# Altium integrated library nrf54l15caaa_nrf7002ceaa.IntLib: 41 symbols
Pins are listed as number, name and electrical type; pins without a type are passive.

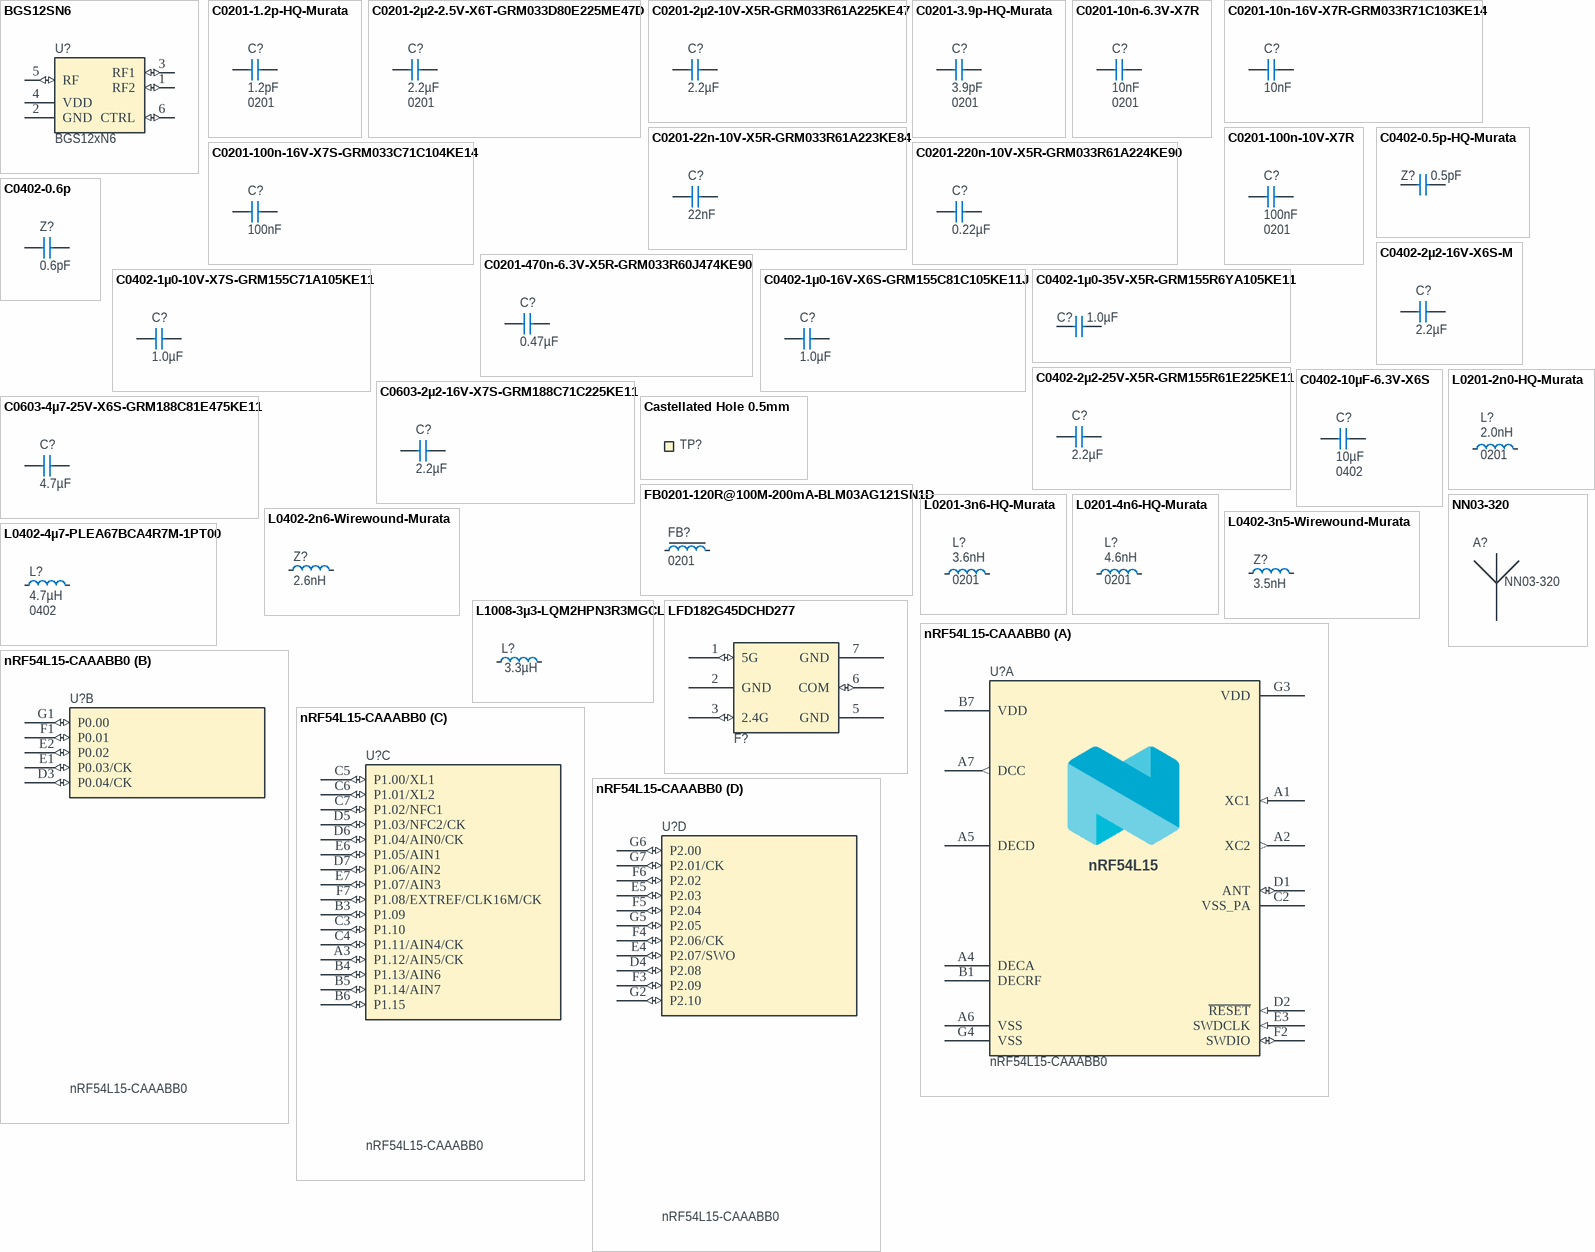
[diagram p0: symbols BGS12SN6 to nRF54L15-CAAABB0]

## BGS12SN6
designator U?, comment BGS12xN6
Wideband SPDT RF Switch, 50MHz-6GHz. Max 30dBm, 1.8-3.5V; Part Number: BGS12SN6; Manufacturer: Infineon Technologies; Manufacturer Part Number: BGS12SN6E6327XTSA1; Component Status: Active; Pad Count: 6; Value: BGS12SN6
footprint TSNP-6-8
pins: 1 RF2 (io), 2 GND (power), 3 RF1 (io), 4 VDD (power), 5 RF (io), 6 CTRL (io), 8 NC hidden

## C0201-1.2p-HQ-Murata
designator C?, comment 1.2pF  Footprint Doc: 0201
Capacitor, NP0, ±0.05pF, 50V; Part Number: C0201-1.2p-HQ-Murata; Manufacturer: Murata; Manufacturer Part Number: GJM0335C1H1R2WB01D; Component Status: Active; Pad Count: 2
footprint CAPC0603X03L_C
pins: 1, 2

## C0201-2µ2-2.5V-X6T-GRM033D80E225ME47D
designator C?, comment 2.2µF  Footprint Doc: 0201
Capacitor, Ceramic, 2.2µF 2.5V X6T 0201,±20%; Part Number: C0201-2µ2-2.5V-X6T-GRM033D80E225ME47D; Manufacturer: Murata; Manufacturer Part Number: GRM033D80E225ME47D; Component Status: Active; Pad Count: 2
footprint CAPC0603X03L_C
pins: 1, 2

## C0201-2µ2-10V-X5R-GRM033R61A225KE47
designator C?, comment 2.2µF
Capacitor, Ceramic, 2.2µF 10V X5R 0201,±10%; Part Number: C0201-2µ2-10V-X5R-GRM033R61A225KE47; Manufacturer: Murata; Manufacturer Part Number: GRM033R61A225KE47D; Pad Count: 2; Component Status: Active
footprint CAPC0603X03L_C
pins: 1, 2

## C0201-3.9p-HQ-Murata
designator C?, comment 3.9pF  Footprint Doc: 0201
Capacitor, NP0, ±0.05pF, 25V; Part Number: C0201-3.9p-HQ-Murata; Manufacturer: Murata; Manufacturer Part Number: GJM0333C1E3R9WB01; Component Status: Active; Pad Count: 2
footprint CAPC0603X03L_C
pins: 1, 2

## C0201-10n-6.3V-X7R
designator C?, comment 10nF  Footprint Doc: 0201
Capacitor, X7R, 6.3V; Part Number: C0201-10n-6.3V-X7R; Manufacturer: Murata; Manufacturer Part Number: GRM033R70J103KA01D; Component Status: Active; Pad Count: 2
footprint CAPC0603X03L_C
pins: 1, 2

## C0201-10n-16V-X7R-GRM033R71C103KE14
designator C?, comment 10nF
Capacitor, Ceramic, 10nF 16V X7R 0201,±10%; Part Number: C0201-10n-16V-X7R-GRM033R71C103KE14; Manufacturer: Murata; Manufacturer Part Number: GRM033R71C103KE14D; Pad Count: 2; Component Status: Active
footprint CAPC0603X03L_C
pins: 1, 2

## C0201-22n-10V-X5R-GRM033R61A223KE84
designator C?, comment 22nF
Capacitor, Ceramic, 22nF 10V X5R 0201,±10%; Part Number: C0201-22n-10V-X5R-GRM033R61A223KE84; Manufacturer: Murata; Manufacturer Part Number: GRM033R61A223KE84D; Pad Count: 2; Component Status: Active
footprint CAPC0603X03L_C
pins: 1, 2

## C0201-100n-10V-X7R
designator C?, comment 100nF  Footprint Doc: 0201
Capacitor, X7R, ±10%; Part Number: C0201-100n-10V-X7R; Manufacturer: N.A.; Pad Count: 2; Component Status: Active
footprint CAPC0603X03L_C
pins: 1, 2

## C0201-100n-16V-X7S-GRM033C71C104KE14
designator C?, comment 100nF
Capacitor, Ceramic, 100nF 16V X7S 0201,±10%; Part Number: C0201-100n-16V-X7S-GRM033C71C104KE14; Manufacturer: Murata; Manufacturer Part Number: GRM033C71C104KE14D; Pad Count: 2; Component Status: Active
footprint CAPC0603X03L_C
pins: 1, 2

## C0201-220n-10V-X5R-GRM033R61A224KE90
designator C?, comment 0.22µF
Capacitor, Ceramic, 0.22µF 10V X5R 0201, ±10%; Part Number: C0201-220n-10V-X5R-GRM033R61A224KE90; Manufacturer: Murata; Manufacturer Part Number: GRM033R61A224KE90D; Pad Count: 2; Component Status: Active
footprint CAPC0603X03L_C
pins: 1, 2

## C0201-470n-6.3V-X5R-GRM033R60J474KE90
designator C?, comment 0.47µF
Capacitor, Ceramic, 0.47µF 6.3V X5R 0201,±10%; Part Number: C0201-470n-6.3V-X5R-GRM033R60J474KE90; Manufacturer: Murata; Manufacturer Part Number: GRM033R60J474KE90D; Pad Count: 2; Component Status: Active
footprint CAPC0603X03L_C
pins: 1, 2

## C0402-0.5p-HQ-Murata
designator Z?, comment 0.5pF
Capacitor, NP0, ±0.05pF, 50V; Part Number: C0402-0.5p-HQ-Murata; Manufacturer: Murata; Manufacturer Part Number: GJM1555C1HR50WB01; Pad Count: 2; Component Status: Active
footprint CAPC1005X04L
pins: 1, 2

## C0402-0.6p
designator Z?, comment 0.6pF
Chip Cap 0402; Part Number: C0402-0.6p; Manufacturer: N.A.; Pad Count: 2; Component Status: Active
footprint CAPC1005X04L
pins: 1, 2

## C0402-1µ0-10V-X7S-GRM155C71A105KE11
designator C?, comment 1.0µF
Capacitor, Ceramic, 1.0µF 10V X7S 0402,±10%; Part Number: C0402-1µ0-10V-X7S-GRM155C71A105KE11; Manufacturer: Murata; Manufacturer Part Number: GRM155C71A105KE11D; Pad Count: 2; Component Status: Active
footprint CAPC1005X04L
pins: 1, 2

## C0402-1µ0-16V-X6S-GRM155C81C105KE11J
designator C?, comment 1.0µF
Capacitor, Ceramic, 1.0µF 16V X6S 0402,±10%; Part Number: C0402-1µ0-16V-X6S-GRM155C81C105KE11J; Manufacturer: Murata; Manufacturer Part Number: GRM155C81C105KE11J; Pad Count: 2; Component Status: Active
footprint CAPC1005X04L
pins: 1, 2

## C0402-1µ0-35V-X5R-GRM155R6YA105KE11
designator C?, comment 1.0µF
Capacitor, Ceramic, 1.0µF 35V X5R 0402,±10%; Part Number: C0402-1µ0-35V-X5R-GRM155R6YA105KE11; Manufacturer: Murata; Manufacturer Part Number: GRM155R6YA105KE11D; Pad Count: 2; Component Status: Active
footprint CAPC1005X04L
pins: 1, 2

## C0402-2µ2-16V-X6S-M
designator C?, comment 2.2µF
CAP MLCC 2.2UF 16V X6S 0402; Part Number: C0402-2µ2-16V-X6S-M; Manufacturer: Taiyo Yuden; Manufacturer Part Number: EMK105CC6225KV-F; Component Status: Active; Pad Count: 2
footprint CAPC1005X04L
pins: 1, 2

## C0402-2µ2-25V-X5R-GRM155R61E225KE11
designator C?, comment 2.2µF
Capacitor, Ceramic, 2.2µF 25V X5R 0402,±10%; Part Number: C0402-2µ2-25V-X5R-GRM155R61E225KE11; Manufacturer: Murata; Manufacturer Part Number: GRM155R61E225KE11D; Pad Count: 2; Component Status: Active
footprint CAPC1005X04L
pins: 1, 2

## C0402-10µF-6.3V-X6S
designator C?, comment 10µF  Footprint Doc: 0402
Capacitor, X6S, ±20%, 6.3V; Part Number: C0402-10µF-6.3V-X6S; Manufacturer: N.A.; Component Status: Active; Pad Count: 2
footprint CAPC1005X04L
pins: 1, 2

## C0603-2µ2-16V-X7S-GRM188C71C225KE11
designator C?, comment 2.2µF
Capacitor, Ceramic, 2.2µF 16V X7S 0603,±10%; Part Number: C0603-2µ2-16V-X7S-GRM188C71C225KE11; Manufacturer: Murata; Manufacturer Part Number: GRM188C71C225KE11D; Pad Count: 2; Component Status: Active
footprint CAPC1608X06L
pins: 1, 2

## C0603-4µ7-25V-X6S-GRM188C81E475KE11
designator C?, comment 4.7µF
Capacitor, Ceramic, 4.7µF 25V X6S 0603,±10%; Part Number: C0603-4µ7-25V-X6S-GRM188C81E475KE11; Manufacturer: Murata; Manufacturer Part Number: GRM188C81E475KE11D; Pad Count: 2; Component Status: Active
footprint CAPC1608X06L
pins: 1, 2

## Castellated Hole 0.5mm
designator TP?, comment CH  (value not drawn)  (no BOM)
Castellated Hole 0.5mm; Manufacturer: N.A.; Component Status: Active; Pad Count: 1
footprint Castellated_Hole_0.5mm
pins: 1

## FB0201-120R@100M-200mA-BLM03AG121SN1D
designator FB?, comment Footprint Doc: 0201  (hidden comment: 120R/0.2A)
Ferrite Bead, 120 Ohm @ 100MHz, 200mA, 500 mOhm Max; Part Number: FB0201-120R@100M-200mA-BLM03AG121SN1D; Manufacturer: Murata; Manufacturer Part Number: BLM03AG121SN1D; Component Status: Active; Pad Count: 2
footprint INDC0603X03L_C
pins: 1, 2

## L0201-2n0-HQ-Murata
designator L?, comment 2.0nH  Footprint Doc: 0201
Inductor, 600mA, ±0.1ｎH, 120mOhm; Part Number: L0201-2n0-HQ-Murata; Manufacturer: Murata; Manufacturer Part Number: LQP03HQ2N0B02; Component Status: Active; Pad Count: 2
footprint INDC0603X03L_C
pins: 1, 2

## L0201-3n6-HQ-Murata
designator L?, comment 3.6nH  Footprint Doc: 0201
Inductor, 500mA, ±0.1ｎH, 170mOhm; Part Number: L0201-3n6-HQ-Murata; Manufacturer: Murata; Manufacturer Part Number: LQP03HQ3N6B02; Component Status: Active; Pad Count: 2
footprint INDC0603X03L_C
pins: 1, 2

## L0201-4n6-HQ-Murata
designator L?, comment 4.6nH  Footprint Doc: 0201
Inductor, 400mA, ±3%, 250mOhm; Part Number: L0201-4n6-HQ-Murata; Manufacturer: Murata; Manufacturer Part Number: LQP03HQ4N6H02; Component Status: Active; Pad Count: 2
footprint INDC0603X03L_C
pins: 1, 2

## L0402-2n6-Wirewound-Murata
designator Z?, comment 2.6nH
Inductor, 850mA, ±0.1nH, 50mΩ; Part Number: L0402-2n6-Wirewound-Murata; Manufacturer: Murata; Manufacturer Part Number: LQW15AN2N6B00; Component Status: Active; Pad Count: 2
footprint INDC1005X04L_WW
pins: 1, 2

## L0402-3n5-Wirewound-Murata
designator Z?, comment 3.5nH
Inductor, 900mA, ±0.2nH, 40mΩ; Part Number: L0402-3n5-Wirewound-Murata; Manufacturer: Murata; Manufacturer Part Number: LQW15AN3N5C10; Component Status: Active; Pad Count: 2
footprint INDC1005X04L_WW
pins: 1, 2

## L0402-4µ7-PLEA67BCA4R7M-1PT00
designator L?, comment 4.7µH  Footprint Doc: 0402
Inductor, 300mA, ±20%, 1.08R; Part Number: L0402-4µ7-PLEA67BCA4R7M-1PT00; Manufacturer: TDK Corporation; Manufacturer Part Number: PLEA67BCA4R7M-1PT00; Component Status: Active; Pad Count: 2
footprint INDC1005X04L
pins: 1, 2

## L1008-3µ3-LQM2HPN3R3MGCL
designator L?, comment 3.3µH
Inductor, 1A, ±20%, 200mOhm; Part Number: L1008-3µ3-LQM2HPN3R3MGCL; Manufacturer: Murata; Manufacturer Part Number: LQM2HPN3R3MGCL; Pad Count: 2; Component Status: Active
footprint INDC2520X10N
pins: 1, 2

## LFD182G45DCHD277
designator F?, comment LFD_5G_Diplexer  (value not drawn)
Signal Conditioning 2.4GHz and 5GHz Diplexer; Part Number: LFD182G45DCHD277; Manufacturer: Murata; Component Status: Active; Pad Count: 6; Value: LFD182G45DCHD277
footprint CAF-50P160X80-6N
pins: 1 5G (io), 2 GND (power), 3 2.4G (io), 5 GND (power), 6 COM (io), 7 GND (power)

## NN03-320
designator A?
Dual-Band GNSS and Wi-Fi/BluetoothAntenna; Manufacturer: Ignion; Component Status: Active; Pad Count: 4
footprint NN03-320
pins: 1 NC hidden, 2 GND hidden, 3 Feed2 hidden, 4 Feed1
3 alternate drawings of the same symbol

## nRF54L15-CAAABB0
designator U?
Multi-protocol Bluetooth Low Energy, IEEE 802.15.4, ANT and 2.4GHz proprietary system-on-chip; Manufacturer: Nordic Semiconductor; Component Status: Active; Pad Count: 47
footprint BGA49C30P7x7_2245X2451X48
part A pins: A1 XC1 (in), A2 XC2 (out), A4 DECA (power), A5 DECD (power), A6 VSS (power), A7 DCC (out), B1 DECRF (power), B7 VDD (power), C2 VSS_PA (power), D1 ANT (io), D2 ~{RESET} (in), E3 SWDCLK (in), F2 SWDIO (io), G3 VDD (power), G4 VSS (power)
part B pins: D3 P0.04/CK (io), E1 P0.03/CK (io), E2 P0.02 (io), F1 P0.01 (io), G1 P0.00 (io)
part C pins: A3 P1.12/AIN5/CK (io), B3 P1.09 (io), B4 P1.13/AIN6 (io), B5 P1.14/AIN7 (io), B6 P1.15 (io), C3 P1.10 (io), C4 P1.11/AIN4/CK (io), C5 P1.00/XL1 (io), C6 P1.01/XL2 (io), C7 P1.02/NFC1 (io), D5 P1.03/NFC2/CK (io), D6 P1.04/AIN0/CK (io), D7 P1.06/AIN2 (io), E6 P1.05/AIN1 (io), E7 P1.07/AIN3 (io), F7 P1.08/EXTREF/CLK16M/CK (io)
part D pins: D4 P2.08 (io), E4 P2.07/SWO (io), E5 P2.03 (io), F3 P2.09 (io), F4 P2.06/CK (io), F5 P2.04 (io), F6 P2.02 (io), G2 P2.10 (io), G5 P2.05 (io), G6 P2.00 (io), G7 P2.01/CK (io)

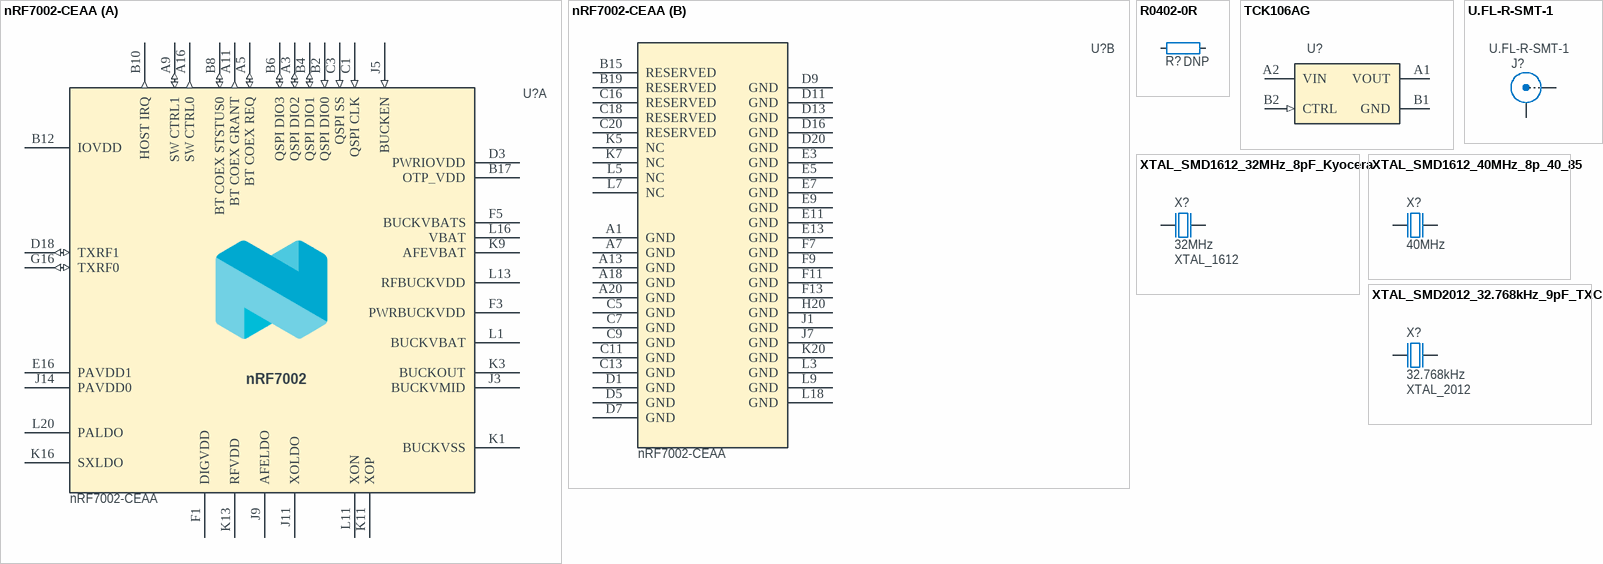
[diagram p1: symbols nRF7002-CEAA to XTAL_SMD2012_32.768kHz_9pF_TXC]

## nRF7002-CEAA
designator U?
Wi-Fi Dual Band Companion chip WLCSP; Manufacturer: Nordic Semiconductor; Component Status: Active; Pad Count: 49
footprint nRF7002_WLCSP_R2
part A pins: A3 QSPI DIO2 (io), A5 BT COEX REQ (io), A9 SW CTRL1 (io), A11 BT COEX GRANT (out), A16 SW CTRL0 (out), B2 QSPI DIO0 (in), B4 QSPI DIO1 (io), B6 QSPI DIO3 (io), B8 BT COEX STSTUS0 (io), B10 HOST IRQ (out), B12 IOVDD, B17 OTP_VDD (power), C1 QSPI CLK (in), C3 QSPI SS (in), D3 PWRIOVDD (power), D18 TXRF1 (io), E16 PAVDD1 (power), F1 DIGVDD (power), F3 PWRBUCKVDD (power), F5 BUCKVBATS (power), G16 TXRF0 (io), J3 BUCKVMID (power), J5 BUCKEN (in), J9 AFELDO (power), J11 XOLDO (power), J14 PAVDD0 (power), K1 BUCKVSS (power), K3 BUCKOUT (power), K9 AFEVBAT (power), K11 XOP, K13 RFVDD (power), K16 SXLDO (power), L1 BUCKVBAT (power), L11 XON, L13 RFBUCKVDD (power), L16 VBAT (power), L20 PALDO (power)
part B pins: A1 GND (power), A7 GND (power), A13 GND (power), A18 GND (power), A20 GND (power), B15 RESERVED, B19 RESERVED, C5 GND (power), C7 GND (power), C9 GND (power), C11 GND (power), C13 GND (power), C16 RESERVED, C18 RESERVED, C20 RESERVED, D1 GND (power), D5 GND (power), D7 GND (power), D9 GND (power), D11 GND (power), D13 GND (power), D16 GND (power), D20 GND (power), E3 GND (power), E5 GND (power), E7 GND (power), E9 GND (power), E11 GND (power), E13 GND (power), F7 GND (power), F9 GND (power), F11 GND (power), F13 GND (power), H20 GND (power), J1 GND (power), J7 GND (power), K5 NC, K7 NC, K20 GND (power), L3 GND (power), L5 NC, L7 NC, L9 GND (power), L18 GND (power)

## R0402-0R
designator R?, comment Assembly: DNP  (hidden comment: 0R)
Resistor, ±5%, 0.063W; Part Number: R0402-0R; Manufacturer: N.A.; Component Status: Active; Pad Count: 2
footprint RESC1005X04L
pins: 1, 2

## TCK106AG
designator U?  (value not drawn)
1.0 A Load Switch IC with Slew Rate Control Driver in Ultra Small Package; Manufacturer: Toshiba; Manufacturer Part Number: TCK106AG,LF; Pad Count: 4
footprint BGA4C40P2X2_76X76X62
pins: A1 VOUT (power), A2 VIN (power), B1 GND (power), B2 CTRL (in)

## U.FL-R-SMT-1
designator J?
Ultra Small Surface Mount Coaxial Connectors, 50 Ohm, SMD; Manufacturer: Hirose; Component Status: Active; Pad Count: 3
footprint COAXIAL RF U.FL-R-SMT-1
pins: 1 X, 2 Y

## XTAL_SMD1612_32MHz_8pF_Kyocera
designator X?, comment 32MHz  Footprint Doc: XTAL_1612
XTAL SMD 1612, 32MHz, Cl=8pF, Tot: ±40ppm, Aging: ±1ppm/year; Part Number: XTAL_SMD1612_32MHz_8pF_Kyocera; Manufacturer: Kyocera; Manufacturer Part Number: CX1612DB32000D0WZRC3; Component Status: Active; Pad Count: 4
footprint BT-XTAL_1612
pins: 1 inp, 2 GND hidden to GND, 3 out, 4 GND hidden to GND

## XTAL_SMD1612_40MHz_8p_40_85
designator X?, comment 40MHz
XTAL SMD 1612, 40MHz, Cl=8pF, Total Tol: ±10ppm, -40-85C; Part Number: XTAL_SMD1612_40MHz_8p_40_85; Manufacturer: Abracon Corporation; Manufacturer Part Number: ABM12W-40.0000MHZ-8-D1X-T3; Pad Count: 4; Component Status: Active
footprint BT-XTAL_1612
pins: 1 inp, 2 GND hidden to GND, 3 out, 4 GND hidden to GND

## XTAL_SMD2012_32.768kHz_9pF_TXC
designator X?, comment 32.768kHz  Footprint Doc: XTAL_2012
XTAL SMD 2012, 32.768kHz, 9pF, ±20ppm; Part Number: XTAL_SMD2012_32.768kHz_9pF_TXC; Manufacturer: TXC Corporation; Manufacturer Part Number: 9HT11-32.768KDZC-T; Component Status: Active; Pad Count: 2
footprint XTAL_2012
pins: 1 inp, 2 out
